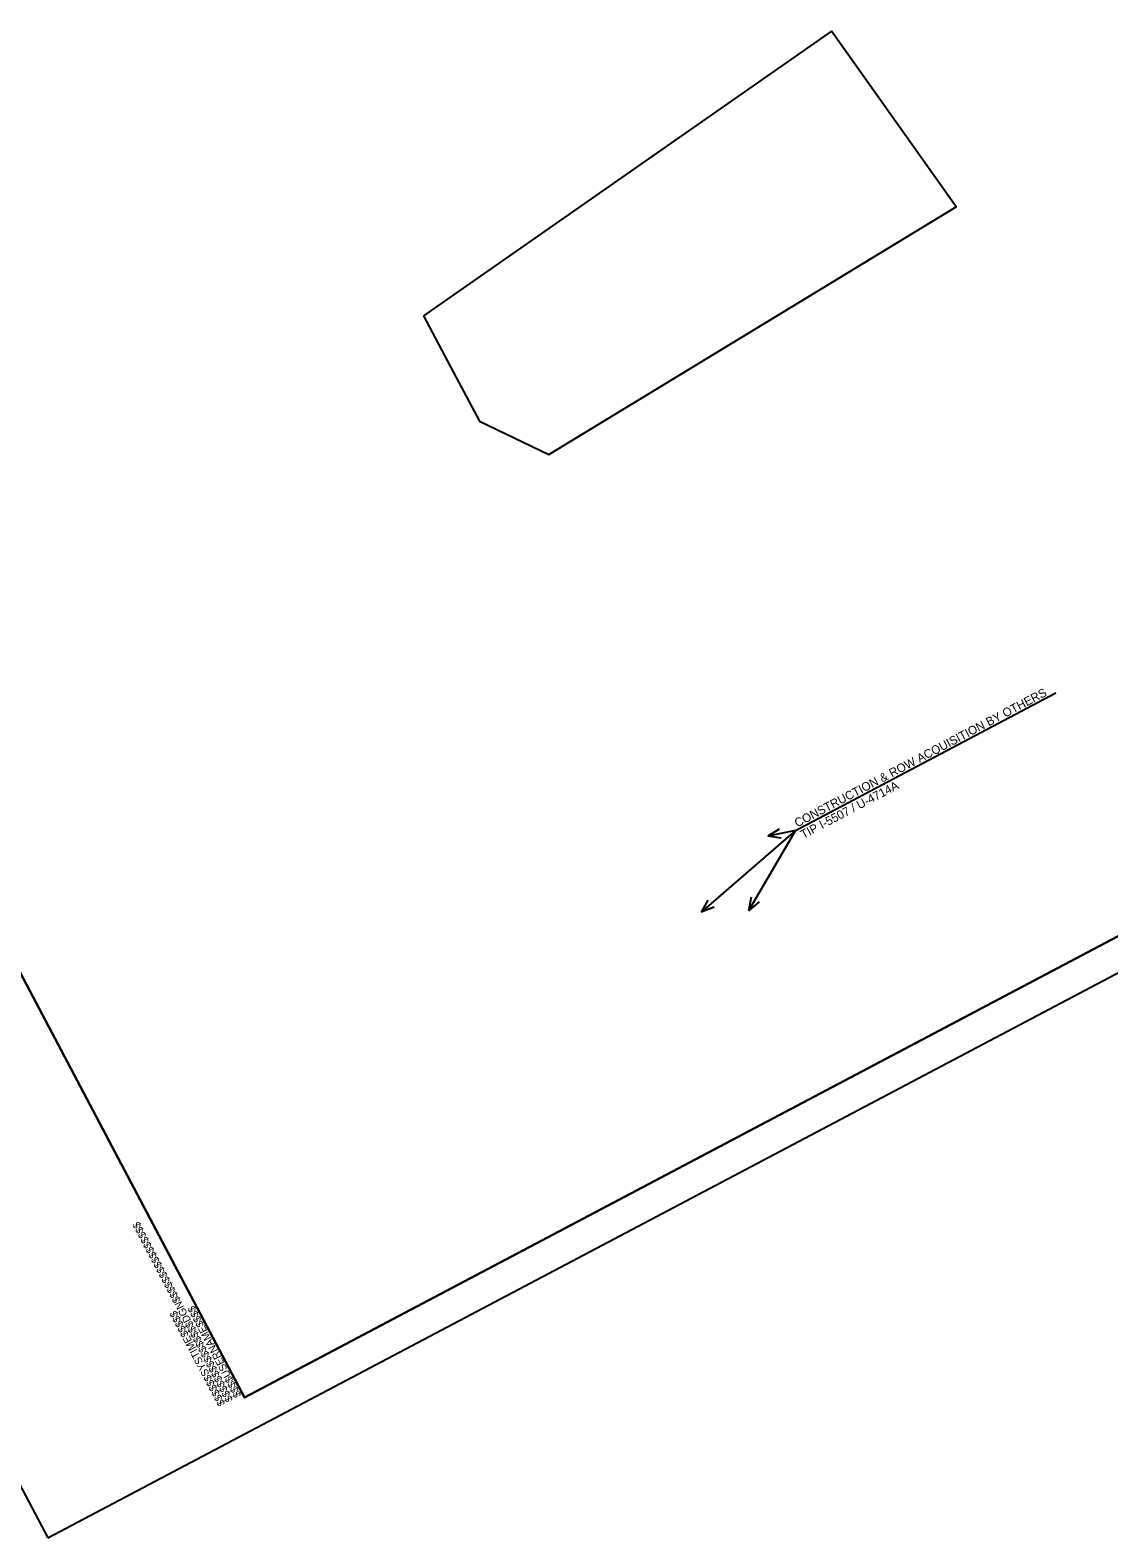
# Model space of a CAD drawing. Extents: x 1486642 to 1489051, y 497560 to 499336.
# Drawn here: x 1487550 to 1488300, y 497582 to 498631 of the extents above; entities that cross this region are included whole.
import ezdxf

# ---------------------------------------------------------------- set-up
doc = ezdxf.new("R2010")
doc.units = 0
for name, color, linetype in [('Prop Horizontal Alignment Station Label', 7, 'Continuous'), ('Scratch_Level_9', 7, 'Continuous'), ('Sheet Clip Boundary CELL', 7, 'Continuous'), ('Sheet Plan CELL', 7, 'Continuous'), ('Sheet Plot Border Outside CELL', 7, 'Continuous')]:
    doc.layers.add(name, color=color, linetype=linetype)

msp = doc.modelspace()

# ---------------------------------------------------------------- linework, layer by layer
at = {"layer": 'Prop Horizontal Alignment Station Label'}
for p, q in [((1488082.4, 498074.2), (1488263.6, 498169.9)), ((1488082.4, 498074.2), (1488016.7, 498017.4)), ((1488082.4, 498074.2), (1488049.7, 498018.3)), ((1488071.1, 498075.1), (1488063, 498070.1)), ((1488082.4, 498074.2), (1488063, 498070.1)), ((1488072.5, 498068.7), (1488063, 498070.1)), ((1488021.4, 498025.7), (1488016.7, 498017.4)), ((1488025.7, 498020.8), (1488016.7, 498017.4)), ((1488051.4, 498027.7), (1488049.7, 498018.3)), ((1488057.1, 498024.4), (1488049.7, 498018.3))]:
    msp.add_line(p, q, dxfattribs=at)
at = {"layer": 'Sheet Clip Boundary CELL'}
for points in [[(1487208.7, 498608.1), (1488222.1, 499143.2), (1488965.4, 498493.7), (1489025.4, 498380), (1487698.9, 497679.6)], [(1487823.6, 498432.2), (1487844.4, 498392.9), (1487862.4, 498358.9), (1487910.8, 498335.8), (1488194.2, 498508), (1488107.4, 498630.3)]]:
    msp.add_lwpolyline(points, close=True, dxfattribs=at)
at = {"layer": 'Sheet Plan CELL'}
msp.add_line((1487698.9, 497679.6), (1487698.9, 497679.6), dxfattribs=at)
for points in [[(1488535.1, 499308.5), (1487208.7, 498608.1), (1487698.9, 497679.6), (1489025.4, 498380)], [(1487698.9, 497679.6), (1487208.7, 498608.1), (1488358.2, 499215.1), (1488428.3, 499082.4), (1488605.2, 499175.8), (1489025.4, 498380)]]:
    msp.add_lwpolyline(points, close=True, dxfattribs=at)
at = {"layer": 'Sheet Plot Border Outside CELL'}
msp.add_lwpolyline([(1487562.2, 497582), (1489050.9, 498368), (1488539.7, 499336.3), (1487050.9, 498550.3)], close=True, dxfattribs=at)

# ---------------------------------------------------------------- texts
at = {"layer": 'Prop Horizontal Alignment Station Label'}
for s, p in [('CONSTRUCTION & ROW ACQUISITION BY OTHERS', (1488083.6, 498076.2)), ('TIP I-5507 / U-4714A', (1488087.8, 498068.2))]:
    msp.add_text(s, height=6, rotation=27.8351, dxfattribs=at).set_placement(p)
at = {"layer": 'Scratch_Level_9'}
for s, p in [('$$$$$$$$$$$$$$$$DGN$$$$$$$$$$$$$$$$', (1487691.1, 497678.1)), ('$$$$$$SYSTIME$$$$$', (1487685.7, 497675.3)), ('$$$$USERNAME$$$$', (1487696.9, 497681.2))]:
    msp.add_text(s, height=5.25, rotation=117.8351, dxfattribs=at).set_placement(p)

doc.saveas('drawing.dxf')
